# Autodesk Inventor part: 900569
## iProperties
Created: 2007-10
Part Number: 900569
Document SubType Name: Modeling
Designer: TH
Density: 1.13 g/cm^3
Mass: 11.4717 g
Surface Area: 58.4741 cm^2
Volume: 10.1519 cm^3
Material: Nylon Composite (Nylon, molybdenum disulphide)
Description: MOTOR SIDE MOUNT COVER
Component Category: Electrical
Author: TH
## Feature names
1. Revolution1
2. Extrusion1
3. Extrusion2
4. Extrusion3
5. Extrusion4
6. Fillet2
7. Fillet3
8. Fillet4
9. Extrusion5
10. Fillet5
